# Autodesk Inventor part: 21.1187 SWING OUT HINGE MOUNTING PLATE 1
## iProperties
Created: 2007-07
Part Number: 21.1187 SWING OUT HINGE MOUNTING PLATE 1
Document SubType Name: Modeling
Designer: Andy Moles
Material: Steel
Mass: 11.5169 g
Surface Area: 27.787 cm^2
Volume: 1.46713 cm^3
Density: 7.85 g/cm^3
Author: Andy Moles
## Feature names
1. Extrusion1
2. Extrusion2
3. Mirror1
4. Fillet1
5. Fillet2
